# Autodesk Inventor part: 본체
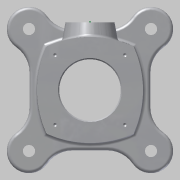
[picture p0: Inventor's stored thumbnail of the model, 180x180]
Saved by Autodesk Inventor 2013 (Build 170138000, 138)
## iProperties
Created: 2016-05
Part Number: 본체
Material: 알루미늄 6061
Document SubType Name: Modeling
Designer: dgall
Mass: 1112.02 g
Surface Area: 865.112 cm^2
Volume: 410.34 cm^3
Density: 2.71 g/cm^3
Author: dgall
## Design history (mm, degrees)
sketch "스케치1"
  geometry: L1 (-14.162, -49)-(14.162, -49); L2 (14.162, 49)-(-14.162, 49); L3 (-49, 14.162)-(-49, -14.162); L4 (49, 14.162)-(49, -14.162); L5 (49.497, 49.497)-(-49.497, -49.497); L6 (-49.497, 49.497)-(49.497, -49.497); L7 (0, 0)-(0, 49); A1 r 18 centre (-49.497, 49.497) between (-34.706, 59.754) and (-59.754, 34.706); A2 r 25 centre (-14.162, 74) between (-34.706, 59.754) and (-14.162, 49); A3 r 25 centre (-74, 14.162) between (-49, 14.162) and (-59.754, 34.706); A4 r 25 centre (-74, -14.162) between (-59.754, -34.706) and (-49, -14.162); A5 r 18 centre (-49.497, -49.497) between (-59.754, -34.706) and (-34.706, -59.754); A6 r 25 centre (-14.162, -74) between (-14.162, -49) and (-34.706, -59.754); A7 r 25 centre (14.162, -74) between (34.706, -59.754) and (14.162, -49); A8 r 18 centre (49.497, -49.497) between (34.706, -59.754) and (59.754, -34.706); A9 r 25 centre (74, -14.162) between (49, -14.162) and (59.754, -34.706); A10 r 25 centre (74, 14.162) between (59.754, 34.706) and (49, 14.162); A11 r 18 centre (49.497, 49.497) between (59.754, 34.706) and (34.706, 59.754); A12 r 25 centre (14.162, 74) between (14.162, 49) and (34.706, 59.754); 1 further point
  constraints: 24 point on circle, 14 end point, 12 centre point, 6 tangent, 3 midpoint, 2 parallel, 1 equal radius, 1 horizontal, 1 perpendicular, 41 other
  dimensions: "d29" = 18 radius of A1; "d30" = 25 radius of A2; "d33" = 360 deg dimension on point (0, 0) A2.centre (derived); "d35" = 98 distance between parallel lines of L3 L4; "d40" = 49 distance of L7.start L7.end; "d41" = 140.00001 distance of L6.start L6.end
extrude "돌출1" new body sketch "스케치1" distance "d42" = 12; taper "d43" = 0 deg
sketch "스케치2"
  geometry: C1 r 25 at (0, 0); 1 further point
  constraints: 1 centre point, 1 coincident
  dimensions: "d44" = 50 diameter of C1
extrude "돌출2" cut sketch "스케치2" distance "d46" = 12; taper "d47" = 0 deg
sketch "스케치3"
  geometry: L1 (-49, 14.162)-(-49, -14.162) reference; L2 (-49, 14.162)-(-49, -14.162) reference; L3 (-14.162, -49)-(14.162, -49) reference; L4 (49, -14.162)-(49, 14.162) reference; L5 (14.162, 49)-(-14.162, 49) reference; L6 (0, 0)-(-35.355, 35.355); L7 (0, 0)-(35.355, -35.355); L8 (0, 0)-(35.355, 35.355); L9 (0, 0)-(-35.355, -35.355); L10 (0, 0)-(0, -43); L11 (0, 0)-(0, 43); L12 (0, 0)-(-43, 0); L13 (0, 0)-(43, 0); C1 r 25 at (0, 0) reference; C2 r 25 at (0, 0) reference; A1 r 18 centre (-49.497, 49.497) between (-34.706, 59.754) and (-59.754, 34.706) reference; A2 r 25 centre (-74, 14.162) between (-49, 14.162) and (-59.754, 34.706) reference; A3 r 25 centre (-74, -14.162) between (-59.754, -34.706) and (-49, -14.162) reference; A4 r 18 centre (-49.497, -49.497) between (-59.754, -34.706) and (-34.706, -59.754) reference; A5 r 25 centre (-14.162, -74) between (-14.162, -49) and (-34.706, -59.754) reference; A6 r 25 centre (14.162, -74) between (34.706, -59.754) and (14.162, -49) reference; A7 r 18 centre (49.497, -49.497) between (34.706, -59.754) and (59.754, -34.706) reference; A8 r 25 centre (74, -14.162) between (49, -14.162) and (59.754, -34.706) reference; A9 r 25 centre (74, 14.162) between (59.754, 34.706) and (49, 14.162) reference; A10 r 18 centre (49.497, 49.497) between (59.754, 34.706) and (34.706, 59.754) reference; A11 r 25 centre (14.162, 74) between (14.162, 49) and (34.706, 59.754) reference; A12 r 25 centre (-14.162, 74) between (-34.706, 59.754) and (-14.162, 49) reference; A13 r 85.579 centre (0, -42.579) between (35.355, 35.355) and (-35.355, 35.355); A14 r 85.579 centre (42.579, 0) between (-35.355, 35.355) and (-35.355, -35.355); A15 r 85.579 centre (0, 42.579) between (-35.355, -35.355) and (35.355, -35.355); A16 r 85.579 centre (-42.579, 0) between (35.355, -35.355) and (35.355, 35.355)
  constraints: 16 end point, 12 point on circle, 4 centre point, 3 collinear, 3 perpendicular, 1 parallel, 1 vertical alignment
  dimensions: "d52" = 45 deg angle of L11 L6; "d53" = 45 deg angle of L10 L9; "d55" = 50 distance of L6.start L6.end; "d56" = 50 distance of L6.start L7.end; "d57" = 50 distance of L6.start L9.end; "d58" = 50 distance of L6.start L8.end; "d61" = 43 distance of L10.start L11.end; "d62" = 43 distance of L10.start L12.end; "d63" = 43 distance of L10.start L10.end; "d64" = 43 distance of L10.start L13.end
extrude "돌출3" join sketch "스케치3" distance "d65" = 98; taper "d66" = 0 deg
sketch "스케치4"
  geometry: C1 r 25 at (0, 0); A1 r 85.579 centre (-42.579, 0) between (35.355, -35.355) and (35.355, 35.355) reference; A2 r 85.579 centre (0, -42.579) between (35.355, 35.355) and (-35.355, 35.355) reference; A3 r 85.579 centre (42.579, 0) between (-35.355, 35.355) and (-35.355, -35.355) reference; A4 r 85.579 centre (0, 42.579) between (-35.355, -35.355) and (35.355, -35.355) reference; 1 further point
  constraints: 1 centre point, 1 coincident
  dimensions: "d67" = 50 diameter of C1
extrude "돌출4" cut sketch "스케치4" distance "d69" = 12; taper "d70" = 0 deg
sketch "스케치5"
  geometry: C1 r 25 at (0, 0) reference; C2 r 35 at (0, 0)
  constraints: 1 centre point, 1 coincident
  dimensions: "d71" = 70 diameter of C2
extrude "돌출5" cut sketch "스케치5" distance "d73" = 86; taper "d74" = 0 deg
node "작업축2"
node "작업 평면1"
node "작업 평면2"
sketch "스케치6"
  geometry: L1 (86, -35.355)-(86, 35.355) reference; L2 (86, -35.355)-(-12, -35.355) reference; L3 (-12, 35.355)-(-12, -35.355) reference; L4 (86, 35.355)-(-12, 35.355) reference; C1 r 20 at (37, 0); 2 further points
  constraints: 1 centre point, 1 horizontal alignment, 1 midpoint
  dimensions: "d77" = 40 diameter of C1; "d79" = 49 distance from line of L3 C1.centre
extrude "돌출6" join sketch "스케치6" stored distance "d80" = 86; taper "d81" = 10 deg
sketch "스케치7"
  geometry: C1 r 20 at (0, 0) reference; C2 r 15 at (0, 0); 1 further point
  constraints: 1 centre point, 1 coincident
  dimensions: "d82" = 30 diameter of C2
extrude "돌출7" cut sketch "스케치7" distance "d84" = 8; taper "d85" = 0 deg
sketch "스케치8"
  geometry: C1 r 15 at (0, 0) reference; C2 r 12.5 at (0, 0); 1 further point
  constraints: 1 centre point, 1 coincident
  dimensions: "d86" = 25 diameter of C2
extrude "돌출8" cut sketch "스케치8" stored distance "d88" = 8; taper "d89" = 0 deg
node "작업 평면3"
sketch "스케치9"
  geometry: 1 further point
node "작업 평면5"
  node "작업 평면4"
sketch "스케치10"
  geometry: L1 (35.355, 12)-(-35.355, 12) reference; C1 r 20 at (0, -37) reference; 2 further points
  constraints: 1 other
  dimensions: "d93" = 49 distance from line of L1 point (-29, -37); "d94" = 29 distance of C1.centre point (-29, -37)
feature "엠보싱1" sketch "스케치10" dims "d29" = 18, "d30" = 25, "d33" = 360 deg (derived), "d35" = 98, "d40" = 49, "d41" = 140.00001, "d95" = 0.5, "d96" = 0
fillet "모깎기1" dims "d97" = 3
fillet "모깎기2" dims "d98" = 3
fillet "모깎기3" dims "d99" = 3
fillet "모깎기4" dims "d100" = 3
chamfer "모따기1" distance "d101" = 1; stored, may be unused: second distance "d102" = 2, angle "d103" = 45 deg
chamfer "모따기2" distance "d104" = 1; stored, may be unused: second distance "d105" = 2, angle "d106" = 45 deg
fillet "모깎기5" dims "d107" = 3
sketch "스케치11"
  geometry: L1 (-46, 0)-(-46, 14.162) reference; L2 (-14.162, 46)-(0, 46) reference; C1 r 9 at (-49.497, 49.497); A1 r 88.579 centre (42.579, 0) between (-37.616, 37.616) and (-46, 0) reference; A2 r 88.579 centre (0, -42.579) between (0, 46) and (-37.616, 37.616) reference; A3 r 28 centre (-14.162, 74) between (-37.171, 58.045) and (-14.162, 46) reference; A4 r 15 centre (-49.497, 49.497) between (-37.171, 58.045) and (-58.045, 37.171) reference; A5 r 28 centre (-74, 14.162) between (-46, 14.162) and (-58.045, 37.171) reference; 1 further point
  constraints: 1 centre point, 1 coincident
  dimensions: "d109" = 18 diameter of C1
extrude "돌출9" cut sketch "스케치11" distance "d111" = 4; taper "d112" = 0 deg
sketch "스케치12"
  geometry: C1 r 9 at (0, 0) reference; C2 r 5 at (0, 0); 1 further point
  constraints: 1 centre point, 1 coincident
  dimensions: "d113" = 10 diameter of C2
extrude "돌출10" cut sketch "스케치12" distance "d115" = 10; taper "d116" = 0 deg
sketch "스케치13"
  geometry: L1 (0, 0)-(-28.284, -28.284); L2 (0, 0)-(0, -40); C1 r 26 at (0, 0) reference; A1 r 3 centre (-33.083, -33.083) between (-35.832, -34.285) and (-34.285, -35.832) reference; A2 r 85.579 centre (0, 42.579) between (-34.285, -35.832) and (34.285, -35.832) reference; A3 r 3 centre (33.083, -33.083) between (34.285, -35.832) and (35.832, -34.285) reference; A4 r 85.579 centre (-42.579, 0) between (35.832, -34.285) and (35.832, 34.285) reference; A5 r 3 centre (33.083, 33.083) between (35.832, 34.285) and (34.285, 35.832) reference; A6 r 85.579 centre (0, -42.579) between (34.285, 35.832) and (-34.285, 35.832) reference; A7 r 3 centre (-33.083, 33.083) between (-34.285, 35.832) and (-35.832, 34.285) reference; A8 r 85.579 centre (42.579, 0) between (-35.832, 34.285) and (-35.832, -34.285) reference; A9 r 40 centre (0, 0) between (-28.284, -28.284) and (0, -40)
  constraints: 4 end point, 2 point on circle, 1 centre point, 1 coincident, 1 vertical
  dimensions: "d120" = 80 diameter of A9; "d122" = 45 deg angle of L2 L1
hole "구멍1" sketch "스케치13" at (-28.284, -28.284) diameter "d124" = 3.242; stored, may be unused: countersink angle "d128" = 90 deg, drill point angle "d130" = 118 deg; dims "d125" = 7, "d126" = 4, "d127" = 2, "d129" = 10
node "작업 평면6"
chamfer "모따기3" distance "d134" = 1; stored, may be unused: second distance "d135" = 2, angle "d136" = 45 deg
node "솔리드1"
pattern_circular "원형 패턴1" dims angle "d118" = 360 deg
pattern_circular "원형 패턴2" dims angle "d132" = 360 deg
mirror "대칭1"
node "투영된 루프1"
node "투영된 루프2"
node "투영된 루프3"
node "투영된 루프4"
node "투영된 루프5"
node "투영된 루프6"
node "투영된 루프7"
node "투영된 루프8"
node "투영된 루프9"
other parameters: "d75" = 0, "d76" = -55, "d90" = -55, "d91" = 0, "d92" = 55
